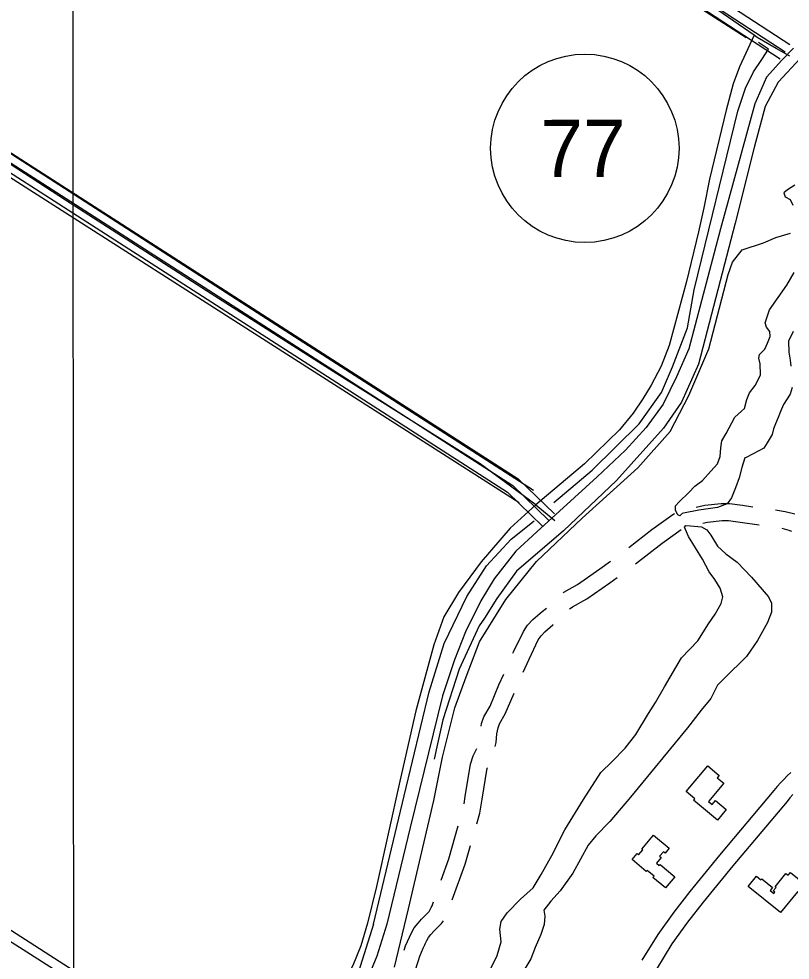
# Model space of a CAD drawing. Extents: x 3297772 to 3335630, y 634068 to 659439.
# Drawn here: x 3307038 to 3308389, y 650944 to 652593 of the extents above; entities that cross this region are included whole.
import ezdxf

# ---------------------------------------------------------------- set-up
doc = ezdxf.new("R2010")
doc.units = 0
for name, color, linetype in [('V-BLDG-OTLN', 7, 'Continuous'), ('V-DTCH-CNTR', 7, 'Continuous'), ('V-GRID-MAJR', 7, 'Continuous'), ('V-ROAD-CNTR', 7, 'Continuous'), ('V-ROAD-IDEN', 7, 'Continuous'), ('V-SITE-OTLN', 7, 'Continuous'), ('V-TOPO-SHOR', 7, 'Continuous')]:
    doc.layers.add(name, color=color, linetype=linetype)

msp = doc.modelspace()

# ---------------------------------------------------------------- linework, layer by layer
at = {"layer": 'V-BLDG-OTLN'}
for points in [[(3308207.2, 651239.2), (3308245, 651284.5), (3308265.3, 651267.6), (3308261.8, 651263.4), (3308273.1, 651254), (3308246.2, 651221.9), (3308252.5, 651216.6), (3308258.4, 651223.8), (3308277.6, 651207.7), (3308262.2, 651189.3), (3308220.3, 651224.3), (3308222.2, 651226.6)], [(3308171, 651070.6), (3308149, 651088.8), (3308151.1, 651091.3), (3308139.1, 651101.2), (3308137.4, 651099.2), (3308112.4, 651120.1), (3308121.2, 651130.7), (3308124, 651128.4), (3308131.2, 651137), (3308129.3, 651138.6), (3308149.8, 651163.2), (3308177.7, 651140), (3308170.6, 651131.3), (3308167.3, 651134), (3308160.7, 651126.1), (3308163.6, 651123.8), (3308155.2, 651113.7), (3308160, 651109.7), (3308161.5, 651111.5), (3308187.2, 651090.2)], [(3308372.7, 651027.3), (3308316, 651073.3), (3308330.3, 651091), (3308338.2, 651084.6), (3308339.6, 651086.4), (3308358.3, 651071.2), (3308354.3, 651066.2), (3308361, 651060.8), (3308362.6, 651062.8), (3308359.7, 651065.2), (3308364.8, 651071.4), (3308363.4, 651072.6), (3308382.1, 651095.7), (3308385.9, 651092.7), (3308389.9, 651097.6), (3308414.8, 651077.4), (3308413.2, 651075.4), (3308433.1, 651059.2), (3308423.2, 651047), (3308402.4, 651063.9)]]:
    msp.add_lwpolyline(points, close=True, dxfattribs=at)
at = {"layer": 'V-DTCH-CNTR'}
for points in [[(3308388.8, 652527.8), (3308364.9, 652541.6), (3308331.7, 652560.8), (3308326.1, 652564.7), (3308199.1, 652652.9), (3307987.9, 652788.1), (3307645.5, 653008.4), (3307371.8, 653185.1), (3307078.1, 653373.2), (3306732.7, 653595.8), (3306651, 653649.6), (3306605.5, 653678.8), (3306578.5, 653692.6), (3306543.8, 653705.6), (3306521.4, 653713.3), (3306499.1, 653723.2), (3306481.9, 653734.3), (3306476.6, 653737.6), (3306417.4, 653775.4), (3306176.8, 653931.3), (3305898.5, 654108.7), (3305640.2, 654272.2)], [(3307943.9, 651741.9), (3307846.1, 651813.3), (3307595.1, 651971.2), (3307374.9, 652111.5), (3307120.1, 652275.6), (3306893.7, 652422.1), (3306614.3, 652598.4), (3306337.1, 652774), (3306058.2, 652958.6)], [(3308326.1, 652564.7), (3308300.8, 652509.3), (3308289.3, 652479.3), (3308277.1, 652433.1), (3308248.1, 652312.3), (3308238.2, 652262.3), (3308229.1, 652220), (3308207.7, 652133.1), (3308177.2, 652020.8), (3308163.4, 651984.6), (3308145.8, 651951.5), (3308131.2, 651927.6), (3308114.3, 651902.2), (3308090.5, 651872.9), (3308029.1, 651813.6), (3307943.9, 651741.9), (3307977, 651714.3)], [(3307402.4, 650733.1), (3307267.7, 650820.5), (3307013.6, 650982.3), (3306706.4, 651177.8), (3306376.9, 651389.4), (3306048.9, 651601.8), (3305749.4, 651795), (3305640.9, 651865.6)], [(3307943.9, 651741.9), (3307898.6, 651701.1), (3307848, 651641.8), (3307808.1, 651587.9), (3307782.8, 651545.6), (3307765.2, 651496.3), (3307733.9, 651380.9), (3307705.7, 651257.8), (3307664.5, 651073.2), (3307649.2, 651008.6), (3307637, 650969.3), (3307623.2, 650934.7), (3307605.6, 650900), (3307588.7, 650870.8), (3307564.2, 650839.2), (3307532.7, 650808.4), (3307485.9, 650772.9), (3307436.7, 650742.9), (3307402.4, 650733.1), (3307369.8, 650725), (3307341.7, 650717.3), (3307293.8, 650704.1), (3307086.2, 650648.4), (3306676.6, 650520.7)]]:
    msp.add_lwpolyline(points, dxfattribs=at)
at = {"layer": 'V-GRID-MAJR'}
msp.add_spline([(3307142.7, 639451.9), (3307140.5, 642480.6), (3307136.1, 648542), (3307131.6, 654603.4), (3307129.4, 657636)], degree=3, dxfattribs=at)
at = {"layer": 'V-ROAD-CNTR'}
for points in [[(3307229.5, 653285.8), (3308380.4, 652535.7)], [(3307237.7, 653298.4), (3308388.6, 652548.3)], [(3307221.3, 653273.3), (3308372.2, 652523.2)], [(3306225.2, 652872.4), (3307913.1, 651787.5), (3307976.4, 651725.9)], [(3306217.1, 652859.8), (3307903.7, 651775.7), (3307965.9, 651715.1)], [(3306209, 652847.1), (3307894.3, 651763.9), (3307955.4, 651704.4)], [(3308395.1, 652541.8), (3308374.8, 652521), (3308347.9, 652491), (3308327.8, 652444.3), (3308267.6, 652225.3), (3308211.7, 652015.1), (3308190.3, 651966.1), (3308167.1, 651918), (3308137, 651877.2), (3308101.1, 651837.7), (3308051.3, 651790.7), (3307945.7, 651694.7), (3307908.7, 651660.4), (3307870.9, 651612.3), (3307847.5, 651573.4), (3307820.4, 651519.4), (3307801.1, 651470), (3307780.4, 651407), (3307723.9, 651176.5), (3307682.8, 651007.2), (3307665.3, 650950.7), (3307644.4, 650900.3)], [(3308225, 651737.8), (3308240, 651740.9), (3308268.4, 651744.2), (3308283.4, 651744.2), (3308306, 651741), (3308324.1, 651738.4)], [(3308106.7, 651667.1), (3308147.3, 651698.7), (3308183.7, 651724.9), (3308187, 651726.7)], [(3308363.7, 651732.7), (3308380.7, 651730.3), (3308397.7, 651725.9)], [(3308236.2, 651709.5), (3308244.8, 651711.2), (3308270.2, 651714.2), (3308281.3, 651714.2), (3308301.8, 651711.3), (3308335.3, 651706.5)], [(3308374.9, 651700.8), (3308387.1, 651697.6), (3308388.3, 651697), (3308391.7, 651695.7)], [(3308118.4, 651638.2), (3308165.3, 651674.7), (3308198.2, 651698.4)], [(3307991.6, 651587.8), (3307992.8, 651588.6), (3308017, 651602.3), (3308056.2, 651629.5), (3308074.8, 651643.1)], [(3308003.1, 651559.2), (3308004, 651560.2), (3308008.1, 651562.8), (3308033, 651576.8), (3308073.7, 651605.1), (3308086.3, 651614.3)], [(3307903.7, 651481.9), (3307904.7, 651484.1), (3307922.1, 651520), (3307929.5, 651531), (3307938.5, 651541), (3307954.8, 651554.9), (3307962.3, 651560.9)], [(3307921.8, 651448.3), (3307932, 651471.6), (3307948.2, 651505), (3307953.2, 651512.5), (3307959.5, 651519.4), (3307973.9, 651531.7), (3307974, 651531.8)], [(3307847.8, 651353.9), (3307848.6, 651358.5), (3307852.5, 651370.1), (3307863.6, 651389.2), (3307879.3, 651426.1), (3307887.7, 651445.2)], [(3307872.7, 651318.4), (3307874.2, 651325.4), (3307875.8, 651340.3), (3307877.8, 651351), (3307880, 651357.8), (3307890.4, 651375.7), (3307905.8, 651411.7)], [(3307818.1, 651217.9), (3307820.2, 651230.9), (3307829.5, 651287.4), (3307833.9, 651301.7), (3307840.2, 651314.8)], [(3307840.4, 651182.9), (3307845.8, 651201.4), (3307849.8, 651226.1), (3307858.7, 651280.5), (3307858.9, 651281.1)], [(3308390.6, 651272.8), (3308384.3, 651266.8), (3308378.2, 651260.7), (3308372.3, 651254.4), (3308366.6, 651248), (3308361, 651241.5), (3308265.8, 651128.2), (3308213.4, 651064.1), (3308185.5, 651028.3), (3308157.4, 650989.1), (3308129.6, 650944)], [(3308394.4, 651234.1), (3308389.1, 651228.2), (3308383.9, 651222.2), (3308288.9, 651109.1), (3308236.9, 651045.4), (3308209.6, 651010.3), (3308182.4, 650972.5), (3308155.1, 650928.2)], [(3307777.9, 651083.9), (3307791.7, 651121.6), (3307803, 651162.7), (3307808, 651179.2)], [(3307797.4, 651049.8), (3307820.3, 651112.4), (3307829.1, 651144.6)], [(3307722.5, 650984.5), (3307726.1, 650991.9), (3307730.6, 651000.7), (3307737.5, 651008.8), (3307743.7, 651015.6), (3307750.1, 651022.2), (3307755.4, 651027.4), (3307756.8, 651029.5), (3307758.8, 651032.7), (3307760.5, 651036), (3307762.1, 651039.3), (3307763.6, 651042.7), (3307764.8, 651046.2)], [(3307749.5, 650971.5), (3307752.9, 650978.5), (3307755.7, 650983.9), (3307760.1, 650989), (3307765.6, 650995.1), (3307771.3, 651001.1), (3307778.5, 651008), (3307781.9, 651013.1)], [(3307712.9, 650961.7), (3307715.7, 650968.9), (3307718.9, 650976.7), (3307722.3, 650984.2)], [(3307733.6, 650928), (3307733.9, 650929), (3307736, 650936.3), (3307738.3, 650943.5), (3307740.8, 650950.7), (3307743.6, 650957.8), (3307746.5, 650964.7), (3307749.7, 650971.8)]]:
    msp.add_lwpolyline(points, dxfattribs=at)
at = {"layer": 'V-ROAD-IDEN'}
msp.add_circle((3308029.7, 652366.4), 165, dxfattribs=at)
at = {"layer": 'V-SITE-OTLN'}
msp.add_lwpolyline([(3307696.3, 650931.9), (3307720.8, 651033.8), (3307765.3, 651223.8), (3307780.6, 651299.5), (3307802, 651386), (3307822, 651440.1), (3307845, 651501.9), (3307891.2, 651576.1), (3307945.1, 651642.6), (3308025.3, 651718.5), (3308122.4, 651806.7), (3308179.4, 651870.1), (3308211.7, 651933.4), (3308247.1, 652015.3), (3308280.8, 652145.1), (3308288.5, 652166.7), (3308305.4, 652188.4), (3308342.5, 652200.8), (3308364.1, 652210.1), (3308390.3, 652217.9)], dxfattribs=at)
at = {"layer": 'V-TOPO-SHOR'}
msp.add_line((3306064, 652928.5), (3307914.7, 651745.9), dxfattribs=at)
for points in [[(3308312.2, 652560.2), (3307994.7, 652764.3), (3307640.2, 652995.9)], [(3307939.6, 651767.1), (3307455.8, 652078.1), (3306952.9, 652402.5), (3306396.1, 652761.5), (3306081.3, 652959.2)], [(3308651.2, 652633), (3308546.2, 652592.4), (3308450.7, 652550.6), (3308407.7, 652524.4), (3308368.3, 652482.6), (3308345.7, 652439.6), (3308326.6, 652368), (3308293.1, 652235.5), (3308228.7, 651988.4), (3308198.8, 651921.6), (3308167.8, 651876.2), (3308085.4, 651784.3), (3307992.3, 651696), (3307910, 651625.5), (3307875.3, 651577.8), (3307853.9, 651543.2), (3307844.3, 651530), (3307809.7, 651453.6), (3307781, 651365.3), (3307770.3, 651317.6), (3307765.5, 651296.1)], [(3307975.6, 651746.1), (3308042.5, 651802.2), (3308124.8, 651883.4), (3308164.2, 651938.3), (3308183.3, 651983.6), (3308209.6, 652051.7), (3308221.5, 652118.5), (3308297.9, 652431.3), (3308311, 652471.9), (3308325.4, 652500.5), (3308339.7, 652522), (3308351.6, 652539.9), (3308333.7, 652551.8)], [(3308397.6, 652301.8), (3308384.5, 652293.4), (3308378.5, 652288.6), (3308380.9, 652281.5), (3308389.2, 652276.7), (3308394, 652267.1)], [(3308192.5, 651724), (3308188.6, 651731.7), (3308188.6, 651740.2), (3308194.8, 651747.2), (3308211.8, 651763.5), (3308222.6, 651774.3), (3308235.7, 651784.4), (3308250.4, 651800.7), (3308262, 651813.8), (3308266.6, 651826.2), (3308268.1, 651841.7), (3308269.6, 651854.1), (3308277.3, 651866.5), (3308292.7, 651895.1), (3308304.3, 651906), (3308309.7, 651910.6), (3308313.6, 651926.1), (3308318.2, 651937.7), (3308328.2, 651950.9), (3308335.1, 651964), (3308337.5, 651969.4), (3308336.6, 651988.8), (3308334.3, 651998.8), (3308335.8, 652005), (3308345.1, 652014.3), (3308349.7, 652025.1), (3308354.3, 652036.8), (3308353.6, 652045.3), (3308348.1, 652053), (3308345.8, 652060.7), (3308353.5, 652083.2), (3308383.6, 652126.5), (3308396.7, 652149)], [(3308394.5, 652045.3), (3308386.8, 652028.3), (3308386.9, 652009), (3308389.2, 651995.1), (3308390.8, 651985)], [(3305480.4, 651982.1), (3306536.3, 651310.2), (3307235.1, 650860.9)], [(3308393.2, 651947.1), (3308389.3, 651935.5), (3308377.8, 651917.7), (3308372.4, 651905.3), (3308368.5, 651894.5), (3308363.9, 651883.6), (3308360.1, 651875.1), (3308357.8, 651865.1), (3308349.3, 651850.4), (3308343.1, 651841.1), (3308334.6, 651836.4), (3308312.2, 651824.8), (3308309.9, 651824), (3308304.5, 651807), (3308299.9, 651789.2), (3308293.7, 651771.4), (3308286.8, 651754.3), (3308279.1, 651743.5), (3308262.1, 651737.3), (3308229.6, 651732.6), (3308202.6, 651727.1), (3308200.2, 651726.3), (3308196.4, 651722.5), (3308192.5, 651724)], [(3307659.3, 651007.2), (3307713, 651231.6), (3307757.2, 651414.3), (3307783.4, 651499), (3307822.8, 651581.4), (3307857.4, 651635.1), (3307900.4, 651681.6), (3307941, 651713.9)], [(3307865.3, 650929.1), (3307876.1, 650952.3), (3307883, 650976.3), (3307880.6, 650998), (3307882.9, 651011.9), (3307893.7, 651026.6), (3307916.9, 651050.6), (3307939.3, 651070.8), (3307953.2, 651094), (3307971.7, 651127.3), (3307994.8, 651172.2), (3308027.2, 651225.6), (3308058, 651272.8), (3308077.3, 651292.2), (3308100.5, 651315.5), (3308119, 651339.5), (3308141.3, 651375.9), (3308153.7, 651395.2), (3308169.1, 651423.1), (3308199.2, 651473.4), (3308227.7, 651503.6), (3308246.2, 651533.1), (3308257.8, 651550.1), (3308268.6, 651568.7), (3308271.7, 651580.3), (3308267, 651595.8), (3308257.7, 651611.2), (3308247.6, 651624.3), (3308236, 651646.7), (3308211.1, 651686.1), (3308204.2, 651702.4), (3308206.5, 651705.5), (3308215, 651704.7), (3308234.3, 651703.2), (3308243.6, 651697.8), (3308250.6, 651688.5), (3308262.2, 651669.2), (3308276.9, 651656.1), (3308296.3, 651641.4), (3308321.9, 651615.2), (3308351.3, 651580.4), (3308356.8, 651569.6), (3308356.8, 651553.4), (3308349.9, 651535.6), (3308332.1, 651503.8), (3308312.9, 651476), (3308274.3, 651438), (3308261.9, 651425.6), (3308250.3, 651402.4), (3308233.4, 651382.2), (3308209.5, 651351.2), (3308109.9, 651229.6), (3308073.6, 651187), (3308048.9, 651161.5), (3308035.8, 651145.2), (3308008.8, 651096.4), (3307986.5, 651065.4), (3307970.3, 651047.6), (3307957.9, 651031.4)], [(3307957.9, 651031.4), (3307959.5, 651021.3), (3307958.7, 651006.6), (3307952.6, 650988.8), (3307942.6, 650966.4), (3307934.9, 650946.2), (3307916.4, 650915.3)], [(3307659.3, 651007.2), (3307633.4, 650923.3), (3307597, 650860.9), (3307554.7, 650811), (3307516.3, 650775.5), (3307468.3, 650748.6), (3307430.9, 650728.5), (3307362.7, 650707.4), (3307283.1, 650686.2), (3306987.4, 650601.8), (3306787.8, 650536.5), (3306640, 650488.5), (3306520.9, 650442.4), (3306411.5, 650396.4), (3306292.5, 650331.1), (3306129.3, 650242.8), (3305985.3, 650154.5), (3305875.9, 650081.5)]]:
    msp.add_lwpolyline(points, dxfattribs=at)

# ---------------------------------------------------------------- texts
at = {"layer": 'V-ROAD-IDEN'}
msp.add_text('77', height=100, rotation=0.0733, dxfattribs=at).set_placement((3307952.2, 652316.3))

doc.saveas('drawing.dxf')
